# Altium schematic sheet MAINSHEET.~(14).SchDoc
size 594 x 420 mm; Scale: 1:1; Разраб.: Иванов; Обозначение документа: АБВГ.123456.001 Э3; Пров.: Петров; Утв.: Сидоров; Наименование организации: ОАО "Концерн "МПО-Гидроприбор"; Перв. применение: АБВГ.123456.000; Наименование изделия 1: Плата; Наименование изделия 2: Схема электрическая; Наименование изделия 3: принципиальная; Нач. отд.: Нач. отд.; Фамилия нач. отд.: Сидоров
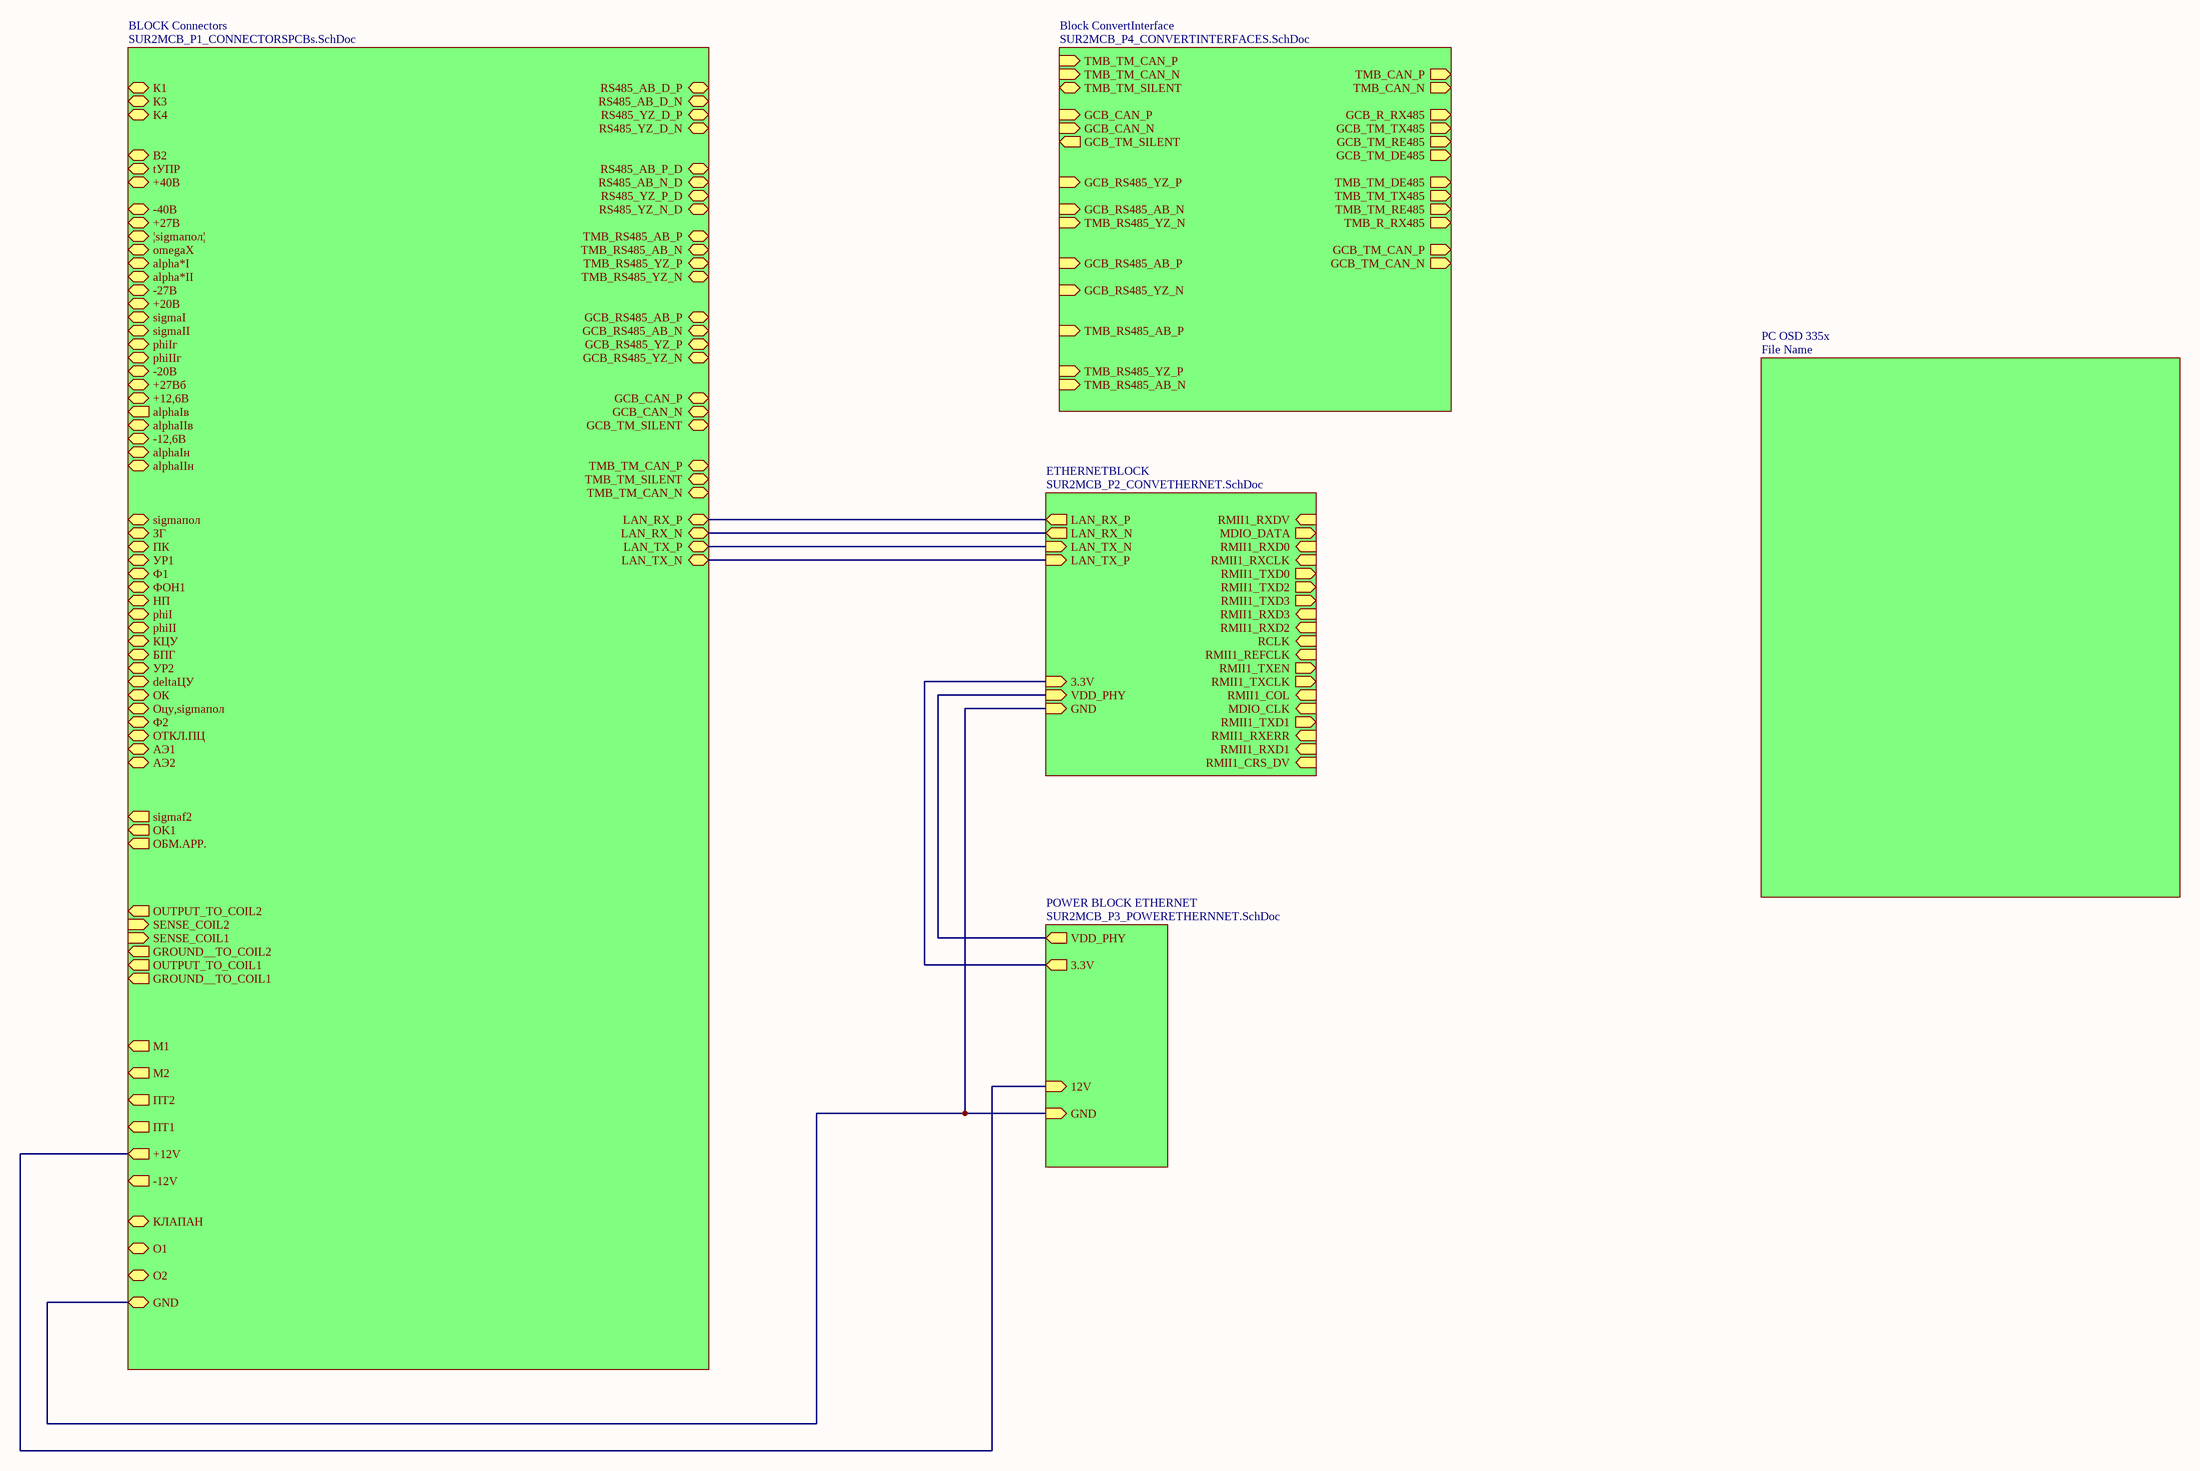
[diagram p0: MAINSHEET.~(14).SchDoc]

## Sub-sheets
BLOCK Connectors = SUR2MCB_P1_CONNECTORSPCBs.SchDoc: tУПР (bidir), B2 (bidir), K4 (bidir), +40В (bidir), К1 (bidir), К3 (bidir), OUTPUT_TO_COIL2 (out), OUTPUT_TO_COIL1 (out), GROUND__TO_COIL1 (out), SENSE_COIL2 (in), GROUND__TO_COIL2 (out), SENSE_COIL1 (in), RS485_YZ_D_N (bidir), RS485_YZ_D_P (bidir), RS485_AB_D_N (bidir), M1 (out), RS485_AB_D_P (bidir), RS485_YZ_N_D (bidir), КЛАПАН (bidir), О1 (bidir), O2 (bidir), RS485_AB_P_D (bidir), RS485_AB_N_D (bidir), RS485_YZ_P_D (bidir), TMB_RS485_AB_N (bidir), TMB_RS485_AB_P (bidir), TMB_RS485_YZ_N (bidir), TMB_RS485_YZ_P (bidir), LAN_RX_P (bidir), LAN_RX_N (bidir), LAN_TX_P (bidir), LAN_TX_N (bidir), GCB_RS485_AB_N (bidir), GCB_RS485_YZ_N (bidir), GCB_RS485_YZ_P (bidir), GCB_RS485_AB_P (bidir), GCB_CAN_P (bidir), GCB_CAN_N (bidir), GCB_TM_SILENT (bidir), TMB_TM_CAN_P (bidir), TMB_TM_SILENT (bidir), TMB_TM_CAN_N (bidir), -40В (bidir), +27В (bidir), ¦sigmaпол¦ (bidir), omegaX (bidir), alpha*II (bidir), alpha*I (bidir), -27В (bidir), +20В (bidir), -20В (bidir), sigmaII (bidir), sigmaI (bidir), phiIIг (bidir), phiIг (bidir), +27Вб (bidir), +12,6В (bidir), -12,6В (bidir), alphaIв (out), alphaIIв (bidir), alphaIIн (bidir), alphaIн (bidir), sigmaпол (bidir), ЗГ (bidir), ПК (bidir), УР1 (bidir), Ф1 (bidir), ФОН1 (bidir), НП (bidir), phiI (bidir), phiII (bidir), ПТ2 (out), +12V (out), КЦУ (bidir), БПГ (bidir), УР2 (bidir), deltaЦУ (bidir), ОК (bidir), Оцу,sigmaпол (bidir), Ф2 (bidir), ОТКЛ.ПЦ (bidir), АЭ1 (bidir), АЭ2 (bidir), ПТ1 (out), M2 (out), -12V (out), sigmaf2 (out), OK1 (out), ОБМ.АРР. (out), GND (bidir)
Block ConvertInterface = SUR2MCB_P4_CONVERTINTERFACES.SchDoc: TMB_TM_TX485 (out), GCB_RS485_YZ_P (in), TMB_R_RX485 (out), GCB_RS485_YZ_N (in), GCB_RS485_AB_P (in), TMB_TM_RE485 (out), GCB_TM_CAN_P (out), TMB_TM_DE485 (out), GCB_TM_CAN_N (out), GCB_RS485_AB_N (in), TMB_RS485_YZ_N (in), GCB_TM_RE485 (out), GCB_CAN_P (in), GCB_R_RX485 (out), GCB_TM_TX485 (out), TMB_RS485_AB_P (in), GCB_TM_SILENT (out), GCB_CAN_N (in), TMB_RS485_YZ_P (in), TMB_RS485_AB_N (in), GCB_TM_DE485 (out), TMB_TM_SILENT (bidir), TMB_TM_CAN_P (in), TMB_TM_CAN_N (in), TMB_CAN_P (out), TMB_CAN_N (out)
ETHERNETBLOCK = SUR2MCB_P2_CONVETHERNET.SchDoc: RMII1_RXDV (in), MDIO_DATA (out), RMII1_RXD0 (in), RMII1_RXCLK (in), RMII1_TXD0 (out), RMII1_TXD2 (out), RMII1_TXD3 (out), RMII1_RXD3 (in), RMII1_RXD2 (in), LAN_RX_P (out), RCLK (in), LAN_RX_N (out), LAN_TX_N (in), RMII1_REFCLK (in), RMII1_TXEN (out), LAN_TX_P (in), RMII1_TXCLK (out), RMII1_COL (in), MDIO_CLK (in), RMII1_TXD1 (out), GND (in), VDD_PHY (in), 3.3V (in), RMII1_RXERR (in), RMII1_RXD1 (in), RMII1_CRS_DV (in)
PC OSD 335x = File Name: no entries
POWER BLOCK ETHERNET = SUR2MCB_P3_POWERETHERNNET.SchDoc: 12V (in), VDD_PHY (out), 3.3V (out), GND (in)

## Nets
(unnamed): sheet BLOCK Connectors/LAN_RX_P, sheet ETHERNETBLOCK/LAN_RX_P
(unnamed): sheet BLOCK Connectors/LAN_RX_N, sheet ETHERNETBLOCK/LAN_RX_N  [a separate net that carries the same name]
(unnamed): sheet BLOCK Connectors/LAN_TX_P, sheet ETHERNETBLOCK/LAN_TX_N  [a separate net that carries the same name]
(unnamed): sheet BLOCK Connectors/LAN_TX_N, sheet ETHERNETBLOCK/LAN_TX_P  [a separate net that carries the same name]
(unnamed): sheet BLOCK Connectors/+12V, sheet POWER BLOCK ETHERNET/12V  [a separate net that carries the same name]
(unnamed): sheet BLOCK Connectors/GND, sheet ETHERNETBLOCK/GND, sheet POWER BLOCK ETHERNET/GND  [a separate net that carries the same name]
(unnamed): sheet ETHERNETBLOCK/VDD_PHY, sheet POWER BLOCK ETHERNET/VDD_PHY  [a separate net that carries the same name]
(unnamed): sheet ETHERNETBLOCK/3.3V, sheet POWER BLOCK ETHERNET/3.3V  [a separate net that carries the same name]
